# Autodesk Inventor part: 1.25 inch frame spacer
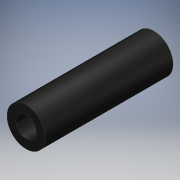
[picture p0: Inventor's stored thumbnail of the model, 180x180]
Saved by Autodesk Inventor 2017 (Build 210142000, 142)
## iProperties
Created: 2016-06
Part Number: 1.25 inch frame spacer
Material: Generic
Document SubType Name: Modeling
Designer: Stan
Density: 1 g/cm^3
Appearance: Glossy - Black
Author: Stan
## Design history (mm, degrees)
sketch "Sketch1"
  geometry: C1 r 2.54 at (0, 0); C2 r 4.763 at (0, 0); 1 further point
  constraints: 2 centre point, 2 coincident
  dimensions: "d0" = 9.525 diameter of C2; "d1" = 5.08 diameter of C1
extrude "Extrusion1" new body sketch "Sketch1" distance "d2" = 31.75; taper "d3" = 0 deg
body "Solid1"
